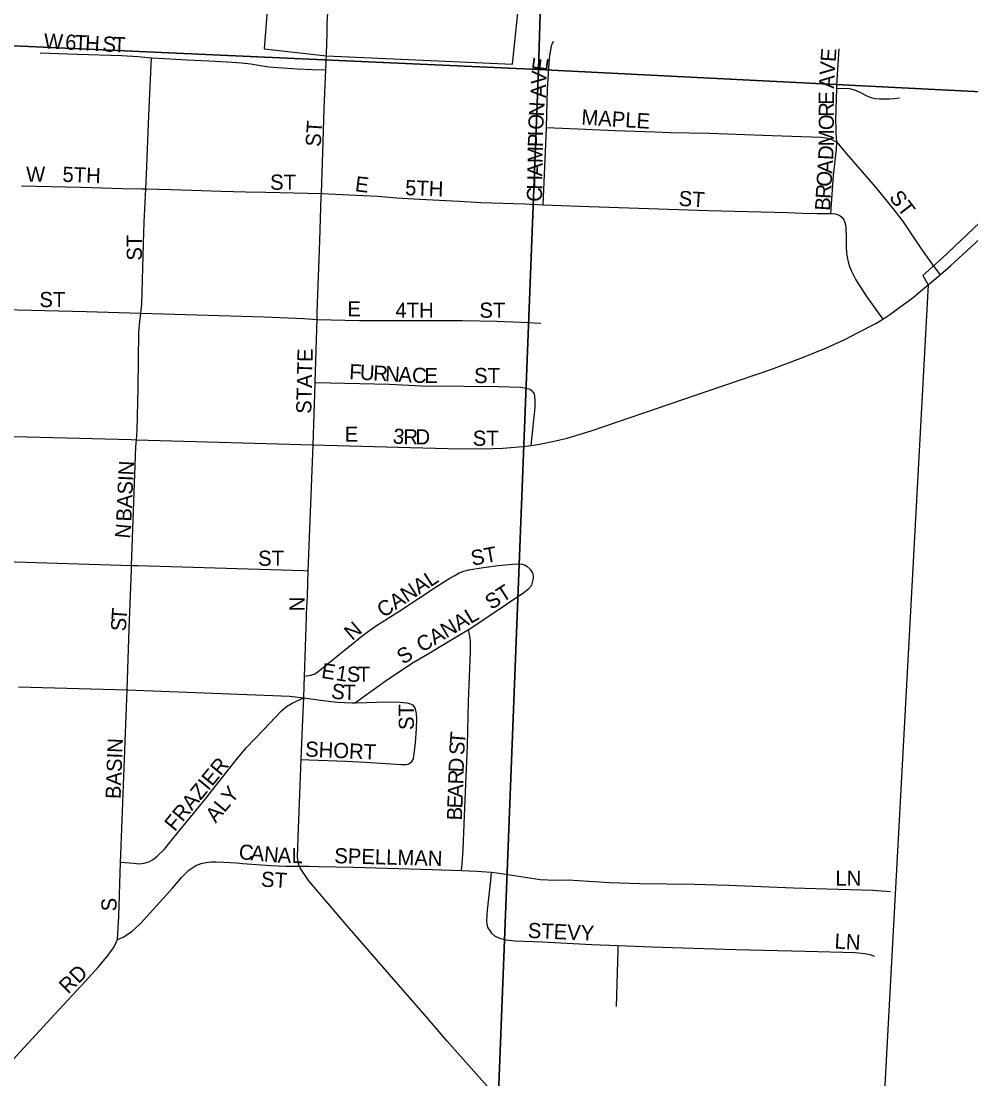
# Model space of a CAD drawing. Extents: x 0 to 34, y 0 to 22.
# Drawn here: x 24.824 to 25.417, y 14.523 to 15.184 of the extents above; entities that cross this region are included whole.
import ezdxf

# ---------------------------------------------------------------- set-up
doc = ezdxf.new("R2010")
doc.units = 0
for name, color, linetype in [('GM_X_City_Street', 7, 'Continuous'), ('GM_X_City_Street_Text', 7, 'Continuous'), ('GM_X_Corporation', 7, 'Continuous'), ('GM_X_County_Road', 7, 'Continuous'), ('GM_X_Section', 7, 'Continuous')]:
    doc.layers.add(name, color=color, linetype=linetype)

msp = doc.modelspace()

# ---------------------------------------------------------------- linework, layer by layer
at = {"layer": 'GM_X_City_Street'}
for points in [[(25.15306, 15.1485), (25.15391, 15.16133), (25.15504, 15.16895), (25.15568, 15.1706), (25.15659, 15.17172)], [(24.8356, 15.1647), (24.85892, 15.16382), (24.88658, 15.16293), (24.89679, 15.16239), (24.90502, 15.16157)], [(25.01411, 15.15399), (25.01444, 15.16396)], [(25.33343, 15.14257), (25.33348, 15.14455), (25.33485, 15.16723)], [(24.90153, 15.07967), (24.90197, 15.08872), (24.90348, 15.12558), (24.90502, 15.16157)], [(24.90502, 15.16157), (24.91326, 15.16108), (24.92749, 15.16037), (24.94086, 15.15963), (24.95241, 15.15913), (24.96133, 15.15843), (24.96716, 15.15781), (24.97193, 15.15693), (24.97821, 15.15586), (24.99623, 15.15471), (25.00554, 15.15422), (25.01411, 15.15399)], [(25.01129, 15.07674), (25.01213, 15.10267), (25.01307, 15.12991), (25.01411, 15.15399)], [(25.15191, 15.1179), (25.15263, 15.14212), (25.15306, 15.1485)], [(25.33349, 15.10873), (25.33309, 15.11464), (25.33292, 15.11675), (25.33281, 15.12292), (25.33308, 15.12911), (25.33343, 15.14257)], [(25.33343, 15.14257), (25.34134, 15.14239), (25.34509, 15.14139), (25.34866, 15.13966), (25.35134, 15.13813), (25.35413, 15.13686), (25.35712, 15.13619), (25.36019, 15.13585), (25.36638, 15.13583), (25.36946, 15.13602), (25.37252, 15.13646)], [(25.1499, 15.06976), (25.15174, 15.11236), (25.15191, 15.1179)], [(25.15191, 15.1179), (25.17644, 15.11693), (25.19487, 15.11616), (25.21965, 15.11523), (25.229, 15.1149), (25.25392, 15.11441), (25.28703, 15.11311), (25.32353, 15.11196), (25.3266, 15.11157), (25.32938, 15.11091), (25.33349, 15.10873)], [(25.32972, 15.06424), (25.33133, 15.08808), (25.33314, 15.10451), (25.33349, 15.10873)], [(25.33349, 15.10873), (25.3394, 15.10154), (25.35762, 15.08067), (25.36927, 15.06642), (25.3748, 15.05907), (25.3828, 15.04723)], [(24.82385, 15.08162), (24.86109, 15.08068), (24.88688, 15.07993), (24.89908, 15.07971), (24.90153, 15.07967)], [(24.89848, 15.00199), (24.89909, 15.00762), (24.90005, 15.04552), (24.9006, 15.05885), (24.90153, 15.07967)], [(24.90153, 15.07967), (24.91736, 15.07931), (24.93626, 15.07861), (24.94865, 15.07816), (24.9641, 15.07782), (24.97648, 15.07768), (25.01129, 15.07674)], [(25.00855, 14.99805), (25.00869, 15.0024), (25.01036, 15.04709), (25.01123, 15.07479), (25.01129, 15.07674)], [(25.01129, 15.07674), (25.04635, 15.07499), (25.0585, 15.074), (25.07258, 15.07313), (25.09743, 15.07187), (25.11102, 15.07118), (25.1384, 15.07021), (25.1499, 15.06976)], [(25.1499, 15.06976), (25.17869, 15.06861), (25.20959, 15.06763), (25.25297, 15.0661), (25.30258, 15.06479), (25.31191, 15.06455), (25.32115, 15.06428), (25.32972, 15.06424)], [(25.32972, 15.06424), (25.33054, 15.06424), (25.33229, 15.06404), (25.33384, 15.06365), (25.33556, 15.06277), (25.33676, 15.06169), (25.33783, 15.0602), (25.33847, 15.0587), (25.33891, 15.05724), (25.33913, 15.05545), (25.33929, 15.04912), (25.33932, 15.04295), (25.3395, 15.03991), (25.33991, 15.03691), (25.34054, 15.03395), (25.3414, 15.03105), (25.34251, 15.02825), (25.34533, 15.02284), (25.35186, 15.01233), (25.3621, 14.99822)], [(25.3828, 15.04723), (25.38858, 15.03868), (25.39411, 15.03122), (25.39797, 15.02599)], [(25.3621, 14.99822), (25.36658, 15.00122), (25.37286, 15.00571), (25.38021, 15.01106)], [(24.73678, 15.00623), (24.82129, 15.00409), (24.86419, 15.00301), (24.89848, 15.00199)], [(24.89564, 14.92282), (24.89608, 14.92856), (24.89677, 14.95514), (24.89718, 14.99008), (24.89786, 14.99679), (24.89848, 15.00199)], [(24.89848, 15.00199), (24.9755, 14.99969), (25.00018, 14.99868), (25.00855, 14.99805)], [(25.00736, 14.95867), (25.00836, 14.99217), (25.00855, 14.99805)], [(25.00855, 14.99805), (25.03493, 14.99733), (25.06258, 14.99732), (25.08406, 14.99745), (25.0994, 14.9974), (25.12089, 14.99705), (25.13621, 14.99644), (25.14849, 14.99569)], [(25.14249, 14.91936), (25.14654, 14.91992), (25.15578, 14.92171), (25.16491, 14.92393), (25.17991, 14.9284), (25.25372, 14.95363), (25.29207, 14.96684), (25.31257, 14.97444), (25.32706, 14.98033), (25.33844, 14.98554), (25.34681, 14.98981), (25.35772, 14.99546), (25.3621, 14.99822)], [(25.00612, 14.91969), (25.00734, 14.95801), (25.00736, 14.95867)], [(25.00736, 14.95867), (25.05382, 14.95758), (25.07378, 14.95666), (25.10046, 14.9564), (25.12188, 14.95615), (25.13585, 14.95565), (25.13912, 14.95515), (25.1418, 14.95448), (25.14331, 14.95331)], [(25.14249, 14.91936), (25.1434, 14.92898), (25.14433, 14.93745), (25.14467, 14.94066), (25.14486, 14.94385), (25.14495, 14.94701), (25.14468, 14.95013), (25.1444, 14.95155), (25.14331, 14.95331)], [(24.73392, 14.92766), (24.7372, 14.9274), (24.77725, 14.92601), (24.85207, 14.92409), (24.89246, 14.92292), (24.89564, 14.92282)], [(24.89262, 14.84433), (24.89526, 14.91846), (24.89564, 14.92282)], [(24.89564, 14.92282), (25.00612, 14.91969)], [(25.00312, 14.84102), (25.00595, 14.9142), (25.00612, 14.91969)], [(25.00612, 14.91969), (25.05918, 14.91821), (25.09037, 14.91731), (25.11223, 14.91719), (25.12475, 14.91755), (25.13724, 14.91863), (25.14249, 14.91936)], [(24.80431, 14.84864), (24.80782, 14.84762), (24.81077, 14.84709), (24.81997, 14.8465), (24.89262, 14.84433)], [(24.88984, 14.76666), (24.89125, 14.80464), (24.89253, 14.84157), (24.89262, 14.84433)], [(24.89262, 14.84433), (24.89665, 14.84421), (25.00006, 14.84111), (25.00312, 14.84102)], [(25.00075, 14.77511), (25.00444, 14.7757), (25.00682, 14.77643), (25.00853, 14.77747), (25.01136, 14.77965), (25.02773, 14.79294), (25.03767, 14.80087), (25.04511, 14.80644), (25.0604, 14.81598), (25.08371, 14.83137), (25.09155, 14.83639), (25.09424, 14.83792), (25.09743, 14.83972), (25.10021, 14.84065), (25.10346, 14.84158), (25.11105, 14.84282), (25.12173, 14.84436), (25.13072, 14.84521), (25.13377, 14.84535), (25.13682, 14.84502), (25.13856, 14.84447), (25.13968, 14.84385), (25.14195, 14.84177)], [(25.00208, 14.81406), (25.00251, 14.8253), (25.00312, 14.84102)], [(25.1032, 14.80419), (25.10527, 14.80544), (25.13783, 14.82749), (25.14093, 14.82997), (25.14281, 14.83201), (25.14387, 14.83616), (25.14388, 14.83768), (25.14372, 14.83879), (25.14346, 14.83962), (25.14195, 14.84177)], [(25.00075, 14.77511), (25.00094, 14.78097), (25.00201, 14.81218), (25.00208, 14.81406)], [(25.03232, 14.75856), (25.03628, 14.76139), (25.05254, 14.773), (25.06856, 14.78371), (25.07762, 14.78879), (25.08969, 14.79606), (25.1032, 14.80419)], [(25.09887, 14.65361), (25.0992, 14.65782), (25.09992, 14.66704), (25.10113, 14.69785), (25.10256, 14.7317), (25.10332, 14.75922), (25.1044, 14.79003), (25.1044, 14.79591), (25.10424, 14.79901), (25.10362, 14.8021), (25.1032, 14.80419)], [(25.00024, 14.76152), (25.00057, 14.76913), (25.00075, 14.77511)], [(24.82204, 14.76856), (24.88984, 14.76666)], [(24.88582, 14.65899), (24.88597, 14.66371), (24.88984, 14.76666)], [(24.88984, 14.76666), (24.99159, 14.7627), (25.00024, 14.76152)], [(24.88582, 14.65899), (24.8886, 14.65875), (24.89402, 14.65829), (24.89748, 14.65793), (24.90057, 14.6582), (24.90353, 14.65912), (24.90623, 14.66065), (24.90868, 14.66256), (24.91313, 14.66701), (24.91911, 14.67425), (24.93893, 14.69845), (24.95824, 14.72306), (24.96426, 14.73024), (24.975, 14.74161), (24.98625, 14.75355), (24.98947, 14.75612), (24.99293, 14.75825), (25.00024, 14.76152)], [(24.99869, 14.72312), (24.99968, 14.74834), (25.00024, 14.76152)], [(25.00024, 14.76152), (25.01077, 14.76011), (25.02114, 14.75896), (25.03031, 14.75855), (25.03232, 14.75856)], [(24.99869, 14.72312), (25.00369, 14.72292), (25.02669, 14.72197), (25.03871, 14.72136), (25.05167, 14.72064), (25.06112, 14.71993), (25.06427, 14.71988), (25.06603, 14.72032), (25.06775, 14.72171), (25.06879, 14.72352), (25.06931, 14.72681), (25.07, 14.7332), (25.07081, 14.7424), (25.07099, 14.7487), (25.07069, 14.75188), (25.07003, 14.75458)], [(25.03232, 14.75856), (25.0396, 14.75861), (25.04586, 14.75886), (25.05528, 14.7591), (25.06043, 14.75891), (25.06473, 14.75845), (25.06689, 14.75784), (25.06818, 14.75724), (25.06913, 14.7562), (25.07003, 14.75458)], [(24.99756, 14.65639), (24.99724, 14.65703), (24.99668, 14.65892), (24.99641, 14.66192), (24.99655, 14.66799), (24.99675, 14.67423), (24.99848, 14.71785), (24.99869, 14.72312)], [(24.88395, 14.61046), (24.88782, 14.61231), (24.89293, 14.61572), (24.89541, 14.61789), (24.89851, 14.62083), (24.91818, 14.64259), (24.92409, 14.64958), (24.92606, 14.65163), (24.92854, 14.6538), (24.93102, 14.65566), (24.93272, 14.65674), (24.93612, 14.65798), (24.93906, 14.6586), (24.94247, 14.65907), (24.94526, 14.65907), (24.95005, 14.65891), (24.95826, 14.65844), (24.96198, 14.65813), (24.97959, 14.6569), (24.98875, 14.65643), (24.99756, 14.65639)], [(24.88395, 14.61046), (24.88474, 14.625), (24.88582, 14.65899)], [(24.99756, 14.65639), (25.00333, 14.65633), (25.00951, 14.65627), (25.03133, 14.65582), (25.08059, 14.65421), (25.09887, 14.65361)], [(25.25611, 14.3938), (25.25387, 14.39477), (25.237, 14.40268), (25.22601, 14.4084), (25.21804, 14.41315), (25.21036, 14.41833), (25.20049, 14.4258), (25.19348, 14.43182), (25.18691, 14.43829), (25.17428, 14.45194), (25.1496, 14.47982), (25.1248, 14.50756), (25.08987, 14.54713), (25.0777, 14.56131), (25.04968, 14.59351), (25.02732, 14.61907), (25.00329, 14.64741), (25.00148, 14.64984), (24.99984, 14.65236), (24.99833, 14.65491), (24.99756, 14.65639)], [(25.09887, 14.65361), (25.10839, 14.6533), (25.11749, 14.65257)], [(25.11749, 14.65257), (25.11695, 14.64751), (25.11597, 14.63825), (25.11492, 14.62899), (25.11461, 14.62593), (25.11446, 14.62253), (25.11477, 14.6199), (25.11539, 14.61789), (25.11631, 14.61634), (25.11756, 14.61448), (25.11956, 14.61278), (25.12266, 14.61138), (25.12684, 14.6103), (25.1321, 14.60983), (25.14929, 14.609), (25.1803, 14.60735), (25.19674, 14.60678)], [(25.11749, 14.65257), (25.12235, 14.6521), (25.13586, 14.65), (25.1481, 14.64798), (25.15765, 14.64761), (25.16555, 14.64776), (25.1784, 14.64699), (25.19155, 14.64622), (25.21012, 14.64556), (25.24427, 14.64505), (25.26601, 14.64454), (25.30634, 14.64282), (25.33428, 14.64204), (25.35601, 14.6414), (25.36694, 14.64064)], [(24.81835, 14.53533), (24.84462, 14.56383), (24.86375, 14.5843), (24.87205, 14.59355), (24.87803, 14.60069), (24.88178, 14.60597), (24.88395, 14.61046)], [(25.19563, 14.56867), (25.19666, 14.60396), (25.19674, 14.60678)], [(25.19674, 14.60678), (25.21754, 14.60604), (25.2703, 14.60437), (25.31375, 14.60329), (25.34479, 14.60243), (25.35095, 14.60181), (25.35399, 14.60115), (25.35696, 14.60023)]]:
    msp.add_lwpolyline(points, dxfattribs=at)
at = {"layer": 'GM_X_Corporation'}
for points in [[(25.62787, 15.25304), (25.39901, 15.0362), (25.38711, 15.02549), (25.39055, 15.01962), (25.35642, 14.38899), (25.00223, 14.39963), (24.6145, 14.42219), (24.62302, 14.65816), (24.28934, 14.51924), (24.31045, 14.95945), (24.31458, 15.18617), (24.61779, 15.17724), (24.72674, 15.17362), (24.73507, 15.37828)], [(24.98077, 15.23431), (24.97542, 15.16708), (25.0144, 15.16284), (25.13069, 15.15756), (25.14735, 15.3176)]]:
    msp.add_lwpolyline(points, dxfattribs=at)
at = {"layer": 'GM_X_County_Road'}
for points in [[(25.01444, 15.16396), (25.01487, 15.17686), (25.01488, 15.18305), (25.01528, 15.18966), (25.0158, 15.19879), (25.01631, 15.20291), (25.01717, 15.20894), (25.01874, 15.21673), (25.02032, 15.2228), (25.02342, 15.23166), (25.02714, 15.24025), (25.03426, 15.25407), (25.05246, 15.28655), (25.06472, 15.30808), (25.07035, 15.31908), (25.07676, 15.33315), (25.08889, 15.36167), (25.1009, 15.39027), (25.1256, 15.44718), (25.14247, 15.48407)], [(25.39797, 15.02599), (25.40452, 15.03161), (25.45692, 15.07993), (25.48476, 15.10464), (25.51919, 15.13599), (25.56734, 15.1799), (25.65676, 15.26147), (25.6937, 15.29466), (25.73289, 15.32999), (25.76052, 15.35507)], [(25.38021, 15.01106), (25.38132, 15.01187), (25.38549, 15.01551), (25.39055, 15.01962), (25.39797, 15.02599)]]:
    msp.add_lwpolyline(points, dxfattribs=at)
at = {"layer": 'GM_X_Section'}
for points in [[(24.14678, 15.53673), (24.15097, 15.53649), (24.644, 15.50874), (25.14407, 15.4826), (25.15684, 15.48182), (25.14694, 15.15424), (24.14401, 15.19968)], [(25.63268, 15.45245), (26.16578, 15.42761), (26.15851, 15.10311), (25.14694, 15.15424), (25.15684, 15.48182)], [(24.14401, 15.19968), (25.14694, 15.15424), (25.10789, 14.15143), (24.10202, 14.20337)], [(25.14694, 15.15424), (26.15851, 15.10311), (26.15237, 14.93685), (26.13408, 14.43121), (26.12359, 14.10638), (25.10789, 14.15143)]]:
    msp.add_lwpolyline(points, close=True, dxfattribs=at)

# ---------------------------------------------------------------- texts
at = {"layer": 'GM_X_City_Street_Text'}
for s, rotation, p in [('W', 357.12416, (24.83765, 15.16743)), ('6', 357.10641, (24.85097, 15.16676)), ('T', 357.10211, (24.85679, 15.16646)), ('H', 357.11061, (24.86345, 15.16613)), ('S', 357.10211, (24.87427, 15.16558)), ('T', 357.60417, (24.88102, 15.16524)), ('E', 85.76057, (25.33264, 15.15877)), ('E', 82.60391, (25.15224, 15.1528)), ('V', 85.84431, (25.33204, 15.15046)), ('V', 85.75552, (25.15164, 15.14463)), ('A', 87.02626, (25.33161, 15.14219)), ('A', 89.78139, (25.15161, 15.13647)), ('E', 89.99561, (25.33161, 15.13218)), ('N', 86.80682, (25.15031, 15.12474)), ('R', 89.99405, (25.33161, 15.12468)), ('O', 87.46392, (25.14994, 15.11645)), ('MAPLE', 356.34728, (25.17356, 15.11992)), ('O', 89.99284, (25.33161, 15.11635)), ('ST', 86.41175, (25.01078, 15.10576)), ('P', 88.98931, (25.14973, 15.10568)), ('I', 88.64439, (25.14984, 15.11233)), ('M', 89.65313, (25.33155, 15.10628)), ('M', 88.96168, (25.14955, 15.09568)), ('D', 87.16666, (25.33113, 15.09751)), ('A', 86.36912, (25.33059, 15.08905)), ('W', 0.00001, (24.82673, 15.08409)), ('5TH', 357.70206, (24.8493, 15.08409)), ('A', 88.97267, (25.1494, 15.08735)), ('O', 86.36732, (25.33006, 15.08074)), ('ST', 0.00001, (24.97923, 15.0791)), ('E', 352.85145, (25.03195, 15.07825)), ('5TH', 357.71079, (25.06346, 15.07576)), ('H', 88.97937, (25.14925, 15.07902)), ('C', 88.95572, (25.14911, 15.07151)), ('ST', 356.42537, (25.23434, 15.06909)), ('R', 86.3667, (25.32959, 15.07325)), ('ST', 307.57762, (25.36567, 15.07419)), ('B', 86.3555, (25.32911, 15.06576)), ('ST', 90, (24.89911, 15.03481)), ('ST', 0.00001, (24.83506, 15.00576)), ('E', 0.00001, (25.02756, 14.99993)), ('4TH', 0.00001, (25.05756, 14.9991)), ('ST', 0.00001, (25.11006, 14.9991)), ('STATE', 88.6634, (25.00494, 14.93902)), ('F', 356.82926, (25.02849, 14.96076)), ('U', 356.85152, (25.03515, 14.96039)), ('R', 356.84172, (25.04347, 14.95994)), ('N', 356.82866, (25.05096, 14.95952)), ('A', 356.85152, (25.05928, 14.95906)), ('C', 357.81992, (25.06778, 14.9586)), ('E', 359.69421, (25.07561, 14.9583)), ('ST', 0.00001, (25.10673, 14.95827)), ('E', 0.00001, (25.02589, 14.9216)), ('3', 353.6805, (25.05562, 14.92069)), ('R', 359.52653, (25.06248, 14.91999)), ('D', 0.0115, (25.07006, 14.91993)), ('ST', 0.00001, (25.10589, 14.9191)), ('BASIN', 87.27516, (24.89245, 14.87157)), ('N', 84.29372, (24.89162, 14.86082)), ('ST', 0.00001, (24.97173, 14.8441)), ('ST', 10.62882, (25.10565, 14.84408)), ('CANAL', 33.14552, (25.04996, 14.81134)), ('ST', 32.74311, (25.11743, 14.81631)), ('N', 90, (25.00078, 14.81565)), ('T', 85.98055, (24.88946, 14.80963)), ('CANAL', 30.57755, (25.07417, 14.78969)), ('S', 86.93838, (24.88911, 14.80301)), ('N', 40.60386, (25.03057, 14.797)), ('S', 33.69847, (25.0624, 14.78213)), ('E', 351.19359, (25.01086, 14.77409)), ('1', 351.21796, (25.01993, 14.77268)), ('S', 359.36787, (25.02715, 14.77167)), ('T', 359.99563, (25.03393, 14.7716)), ('S', 352.35662, (25.01703, 14.76135)), ('T', 359.48117, (25.02492, 14.76037)), ('ST', 90, (25.06911, 14.74148)), ('T', 85.34981, (25.1009, 14.73224)), ('BASIN', 87.79868, (24.88578, 14.69822)), ('SHORT', 357.45186, (25.00097, 14.72493)), ('S', 87.21262, (25.10058, 14.72566)), ('FRAZIER', 50.57213, (24.91965, 14.67758)), ('D', 87.9436, (25.10019, 14.71487)), ('R', 87.93552, (25.09992, 14.70737)), ('ALY', 50.43984, (24.94527, 14.68291)), ('A', 87.95493, (25.09963, 14.69904)), ('E', 87.93323, (25.09938, 14.69237)), ('B', 87.93552, (25.09911, 14.68488)), ('C', 355.16174, (24.95938, 14.66076)), ('A', 355.14197, (24.96685, 14.66012)), ('N', 355.14197, (24.97516, 14.65942)), ('A', 357.24567, (24.98384, 14.65869)), ('L', 359.90728, (24.99264, 14.65827)), ('SPELLMAN', 358.43147, (25.01928, 14.65827)), ('ST', 356.42537, (24.97332, 14.64367)), ('LN', 0.00001, (25.33256, 14.6441)), ('S', 90, (24.88328, 14.62815)), ('STEVY', 357.4567, (25.14014, 14.6116)), ('LN', 356.98842, (25.33182, 14.60493)), ('RD', 45, (24.85297, 14.57608))]:
    msp.add_text(s, height=0.00947, rotation=rotation, dxfattribs=at).set_placement(p)

doc.saveas('drawing.dxf')
